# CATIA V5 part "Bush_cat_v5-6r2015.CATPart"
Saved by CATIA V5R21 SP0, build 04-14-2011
Part number: Bush
Bounding box of the stored display mesh (mm): x 75 to 115, y 10 to 50, z 160 to 210
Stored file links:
  E:\cadcim\Projects\CATIA V5-6R2015_Menuscript\WebResources\CATIA V5-6r2015_partfiles\Tutorials\c12_catia_v5_6r2015_tut\c12tut2\Bush_cat_v5-6r2015.CATPart
  E:\cadcim\Projects\CATIA V5-6R2015_Menuscript\WebResources\CATIA V5-6r2015_partfiles\Tutorials\c12_catia_v5_6r2015_tut\c12tut2\Assembly_cat_v5-6r2015.CATProduct
  D:\CATIA V5R21 E-RESOURCES\CATIA-V5R21\catia-v5r21-Tut\c12-catia-v5r21-tut\c12-catia-v5r21-tut02\Guide Pillar.CATPart
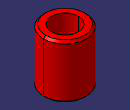
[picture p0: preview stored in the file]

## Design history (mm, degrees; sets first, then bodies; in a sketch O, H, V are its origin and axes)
Set1
  DatumSurface1: linked copy from another document
  DatumCurve1: linked copy from another document
Body1 (main body)
  Sketch1 on face of DatumSurface1, origin (0, 0, 200), H (1, 0, 0), V (0, 1, 0)
    projected circle E1 centre (95, 30) radius 12.5 from edge of DatumCurve1
    circle A1 centre (95, 30) radius 20
    point P1 (95, 30)
    radius A1 = 20
    concentricity: P1 E1, A1 E1
  Pad1: profile Sketch1, direction (0, 0, 1), length 10, opposite side length 40
  Chamfer1: length 2, angle 45, on face of Pad1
